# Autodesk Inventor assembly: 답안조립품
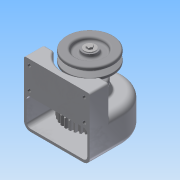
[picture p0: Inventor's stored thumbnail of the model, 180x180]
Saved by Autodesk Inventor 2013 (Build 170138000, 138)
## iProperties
Created: 2015-02
Part Number: 답안조립품
Document SubType Name: Assembly
Designer: Administrator
Author: Administrator
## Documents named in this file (14)
- C:\Documents and Settings\Administrator\바탕 화면\450214V1004\답안조립품.iam
- C:\Documents and Settings\Administrator\바탕 화면\450214V1004\1-본체.ipt
- C:\Documents and Settings\Administrator\바탕 화면\450214V1004\베어링 6001.ipt
- C:\Documents and Settings\Administrator\바탕 화면\450214V1004\축.ipt
- C:\Documents and Settings\Administrator\바탕 화면\450214V1004\키5x5.ipt
- C:\Documents and Settings\Administrator\바탕 화면\450214V1004\M3x0.5.ipt
- C:\Documents and Settings\Administrator\바탕 화면\450214V1004\5-스퍼기어.ipt
- C:\Documents and Settings\Administrator\바탕 화면\450214V1004\오일실.ipt
- C:\Documents and Settings\Administrator\바탕 화면\450214V1004\축커버.ipt
- C:\Documents and Settings\Administrator\바탕 화면\450214V1004\와샤.ipt
- C:\Documents and Settings\Administrator\바탕 화면\450214V1004\키4x4.ipt
- C:\Documents and Settings\Administrator\바탕 화면\450214V1004\M5x0.8.ipt
- M5x0.8.ipt
- C:\Documents and Settings\Administrator\바탕 화면\450214V1004\4-v-벨트풀리.ipt
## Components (7 placed, 4 different names)
1. 1-본체:1 — 각도:6
2. M5x0.8:1 — 각도:6
3. 4-v-벨트풀리:1 — 각도:4
4. M3x0.5:1
5. M3x0.5:2
6. M3x0.5:3
7. M3x0.5:4
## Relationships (2: Angle 2)
- 각도:4 [Angle]: 4-v-벨트풀리:1
- 각도:6 [Angle]: 1-본체:1 ↔ M5x0.8:1
